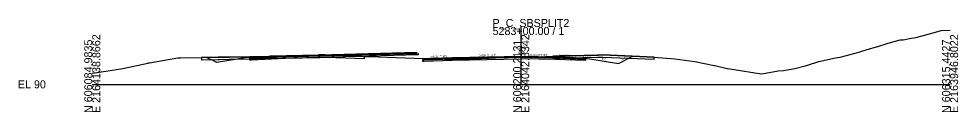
# Model space of a CAD drawing. Extents: x -26 to 1303, y -10 to 12033.
# Drawn here: x -25.7 to 302.8, y 1990.3 to 2022.8 of the extents above; entities that cross this region are included whole.
import ezdxf

# ---------------------------------------------------------------- set-up
doc = ezdxf.new("R2010")
doc.units = 0
for name, color, linetype in [('RD_GPK_XS_Cell', 7, 'Continuous'), ('RD_XS_Base', 7, 'Continuous'), ('RD_XS_ExGround', 7, 'Continuous'), ('RD_XS_ExPaveRet', 7, 'Continuous'), ('RD_XS_Greenside', 7, 'Continuous'), ('RD_XS_Pave', 7, 'Continuous'), ('RD_XS_PaveOvlay_CP', 7, 'Continuous'), ('RD_XS_TieSlope', 7, 'Continuous'), ('RD_XS_TX_Elev_EX', 7, 'Continuous'), ('RD_XS_TX_Elev_PR', 7, 'Continuous'), ('RD_XS_TX_ShdSlope', 7, 'Continuous'), ('RD_XS_TX_Slope', 7, 'Continuous')]:
    doc.layers.add(name, color=color, linetype=linetype)

msp = doc.modelspace()

# ---------------------------------------------------------------- linework, layer by layer
at = {"layer": 'RD_GPK_XS_Cell'}
for p, q in [((150, 2000), (150, 2020)), ((0, 2000), (150, 2000)), ((150, 2000), (300, 2000))]:
    msp.add_line(p, q, dxfattribs=at)
at = {"layer": 'RD_XS_Base'}
for p, q in [((79.53, 2009.89), (114.03, 2010.79)), ((113.53, 2010.78), (113.53, 2010.78)), ((114.03, 2010.79), (114.03, 2010.29)), ((114.03, 2010.76), (114.03, 2010.76)), ((55.52, 2009.1), (55.03, 2009.08)), ((55.03, 2009.08), (55.03, 2009.07)), ((55.03, 2009.07), (55.03, 2008.58)), ((55.03, 2008.58), (55.52, 2008.6)), ((55.53, 2009.1), (55.52, 2009.1)), ((55.52, 2008.6), (55.53, 2008.6)), ((67.43, 2009.58), (55.53, 2009.1)), ((55.53, 2008.6), (67.43, 2009.08)), ((67.53, 2009.58), (67.43, 2009.58)), ((67.43, 2009.08), (67.53, 2009.08)), ((79.53, 2009.89), (67.53, 2009.58)), ((67.53, 2009.08), (79.53, 2009.39)), ((114.03, 2010.29), (79.53, 2009.39)), ((79.53, 2009.39), (79.53, 2010.05)), ((79.53, 2010.05), (79.53, 2010.05)), ((79.53, 2010.05), (79.53, 2010.05)), ((79.53, 2010.05), (79.53, 2009.89)), ((79.53, 2009.89), (79.53, 2009.89)), ((79.53, 2009.39), (79.53, 2009.89)), ((79.53, 2009.89), (79.53, 2009.89)), ((79.53, 2009.89), (79.53, 2009.89)), ((79.53, 2009.39), (79.53, 2009.39)), ((103.53, 2010.52), (103.53, 2010.52)), ((103.53, 2010.52), (103.53, 2010.52)), ((103.53, 2010.02), (103.53, 2010.02)), ((103.53, 2010.02), (103.53, 2010.02)), ((116, 2008.55), (115.5, 2008.53)), ((115.5, 2008.53), (115.5, 2008.53)), ((115.5, 2008.53), (115.5, 2008.03)), ((115.5, 2008.03), (116, 2008.05)), ((126, 2008.95), (116, 2008.55)), ((116, 2008.55), (116, 2008.55)), ((116, 2008.05), (126, 2008.45)), ((116, 2008.05), (116, 2008.05)), ((150, 2009.43), (126, 2008.95)), ((126, 2008.95), (126, 2008.95)), ((126, 2008.45), (150, 2008.93)), ((126, 2008.45), (126, 2008.45)), ((150, 2008.93), (150, 2009.59)), ((150, 2009.59), (150, 2009.59)), ((150, 2009.59), (150, 2009.59)), ((150, 2009.59), (150, 2009.43)), ((150, 2009.43), (150, 2009.43)), ((150, 2009.43), (162, 2009.19)), ((150, 2009.43), (150, 2009.43)), ((150, 2008.93), (150, 2009.43)), ((150, 2009.43), (150, 2009.43)), ((150, 2009.43), (150, 2009.43)), ((162, 2008.69), (150, 2008.93)), ((150, 2008.93), (150, 2008.93)), ((150, 2008.93), (150, 2008.93)), ((162, 2009.19), (162, 2009.19)), ((162, 2009.19), (172, 2008.79)), ((172.5, 2008.27), (162, 2008.69)), ((162, 2008.69), (162, 2008.69)), ((172, 2008.79), (172, 2008.79)), ((172, 2008.79), (172.5, 2008.77)), ((172.5, 2008.77), (172.5, 2008.77)), ((172.5, 2008.77), (172.5, 2008.27))]:
    msp.add_line(p, q, dxfattribs=at)
at = {"layer": 'RD_XS_ExGround'}
msp.add_lwpolyline([(0, 2003.91), (5.51, 2004.71), (10.68, 2005.49), (19.48, 2007.43), (19.71, 2007.48), (20.06, 2007.55), (29.93, 2009.27), (30.97, 2009.28), (38.21, 2009.33), (44.09, 2009.45), (47.86, 2009.5), (47.89, 2009.5), (47.9, 2009.5), (61.79, 2009.77), (62.04, 2009.77), (62.41, 2009.78), (79.01, 2010.23), (79.28, 2010.26), (79.38, 2010.25), (79.88, 2010.27), (81.37, 2010.25), (85.15, 2010.12), (95.16, 2009.74), (100.25, 2009.59), (106.15, 2009.38), (112.75, 2009.12), (123.07, 2008.79), (126.49, 2008.63), (131.61, 2008.78), (143.32, 2009.31), (149.88, 2009.45), (152.23, 2009.52), (155.84, 2009.64), (161.06, 2009.83), (163.66, 2009.9), (166.43, 2009.96), (167.1, 2010), (176.71, 2010.23), (176.88, 2010.21), (178.4, 2010.24), (178.5, 2010.24), (178.6, 2010.24), (196.52, 2009.52), (203.73, 2008.86), (210.73, 2008), (217.55, 2006.61), (217.67, 2006.59), (218.16, 2006.47), (222.09, 2005.5), (222.14, 2005.5), (226.04, 2004.93), (231.73, 2003.98), (234.22, 2003.68), (239.82, 2004.66), (241.79, 2004.82), (245.68, 2005.49), (249.28, 2006.45), (249.39, 2006.46), (250.1, 2006.68), (254.09, 2007.99), (259.97, 2009.26), (261.51, 2009.5), (268.51, 2011.34), (268.73, 2011.4), (268.79, 2011.42), (272.16, 2012.55), (274.77, 2013.22), (278.29, 2014.34), (282.51, 2015.5), (283.61, 2015.5), (285.83, 2015.94), (288.03, 2016.38), (294.04, 2018), (296.83, 2018.78), (300, 2018.95)], dxfattribs=at)
at = {"layer": 'RD_XS_ExPaveRet'}
for points in [[(85.4, 2010.11), (85.15, 2010.12), (81.39, 2010.25), (81.37, 2010.25), (81.36, 2010.25), (79.88, 2010.27), (79.58, 2010.26), (79.38, 2010.25), (79.28, 2010.26), (79.01, 2010.23), (79.01, 2010.23), (79.01, 2010.23), (79, 2010.23), (62.41, 2009.78), (62.26, 2009.78), (62.04, 2009.77), (61.89, 2009.77), (61.79, 2009.77), (55.33, 2009.64), (55.05, 2009.64), (48.13, 2009.5), (48.02, 2009.5), (47.91, 2009.5), (44.5, 2009.45), (44.18, 2009.45), (44.09, 2009.45), (38.38, 2009.33), (38.21, 2009.33), (38.21, 2009.33), (38.21, 2009.33), (38.21, 2009.28), (38.21, 2008.58), (38.21, 2008.58), (38.21, 2008.58), (38.38, 2008.58), (44.09, 2008.7), (44.18, 2008.7), (44.5, 2008.7), (47.91, 2008.75), (48.02, 2008.75), (48.13, 2008.75), (55.05, 2008.89), (55.33, 2008.89), (61.79, 2009.02), (61.89, 2009.02), (62.04, 2009.02), (62.26, 2009.03), (62.41, 2009.03), (79, 2009.48), (79.01, 2009.48), (79.01, 2009.48), (79.01, 2009.48), (79.28, 2009.51), (79.38, 2009.5), (79.58, 2009.51), (79.88, 2009.52), (81.36, 2009.5), (81.37, 2009.5), (81.39, 2009.5), (85.15, 2009.37), (85.4, 2009.36), (95.16, 2008.99), (95.16, 2009.04), (95.16, 2009.74), (85.4, 2010.11)], [(85.4, 2010.11), (85.15, 2010.12), (81.39, 2010.25), (81.37, 2010.25), (81.36, 2010.25), (79.88, 2010.27), (79.58, 2010.26), (79.38, 2010.25), (79.28, 2010.26), (79.01, 2010.23), (79.01, 2010.23), (79.01, 2010.23), (79, 2010.23), (62.41, 2009.78), (62.26, 2009.78), (62.04, 2009.77), (61.89, 2009.77), (61.79, 2009.77), (55.33, 2009.64), (55.05, 2009.64), (48.13, 2009.5), (48.02, 2009.5), (47.91, 2009.5), (44.5, 2009.45), (44.18, 2009.45), (44.09, 2009.45), (38.38, 2009.33), (38.21, 2009.33), (38.21, 2009.28), (38.21, 2008.58), (38.38, 2008.58), (44.09, 2008.7), (44.18, 2008.7), (44.5, 2008.7), (47.91, 2008.75), (48.02, 2008.75), (48.13, 2008.75), (55.05, 2008.89), (55.33, 2008.89), (61.79, 2009.02), (61.89, 2009.02), (62.04, 2009.02), (62.26, 2009.03), (62.41, 2009.03), (79, 2009.48), (79.01, 2009.48), (79.01, 2009.48), (79.01, 2009.48), (79.28, 2009.51), (79.38, 2009.5), (79.58, 2009.51), (79.88, 2009.52), (81.36, 2009.5), (81.37, 2009.5), (81.39, 2009.5), (85.15, 2009.37), (85.4, 2009.36), (95.16, 2008.99), (95.16, 2009.04), (95.16, 2009.74), (85.4, 2010.11)], [(196.52, 2009.52), (196.52, 2009.52), (178.6, 2010.24), (178.6, 2010.24), (178.5, 2010.24), (178.4, 2010.24), (176.88, 2010.21), (176.88, 2010.21), (176.71, 2010.23), (176.71, 2010.23), (176.71, 2010.23), (176.71, 2010.23), (167.1, 2010), (167.1, 2010), (166.43, 2009.96), (163.66, 2009.9), (163.66, 2009.9), (161.06, 2009.83), (161.06, 2009.83), (161.06, 2009.08), (163.66, 2009.15), (163.66, 2009.15), (166.43, 2009.21), (167.1, 2009.25), (167.1, 2009.25), (176.71, 2009.48), (176.71, 2009.48), (176.71, 2009.48), (176.71, 2009.48), (176.88, 2009.46), (176.88, 2009.46), (178.4, 2009.49), (178.5, 2009.49), (178.6, 2009.49), (178.6, 2009.49), (196.52, 2008.77), (196.52, 2008.77), (196.52, 2008.77), (196.52, 2009.52), (196.52, 2009.52), (196.52, 2009.52)], [(196.52, 2009.52), (178.6, 2010.24), (178.5, 2010.24), (178.4, 2010.24), (176.88, 2010.21), (176.71, 2010.23), (167.1, 2010), (166.43, 2009.96), (163.66, 2009.9), (161.06, 2009.83), (161.06, 2009.08), (163.66, 2009.15), (166.43, 2009.21), (167.1, 2009.25), (176.71, 2009.48), (176.88, 2009.46), (178.4, 2009.49), (178.5, 2009.49), (178.6, 2009.49), (196.52, 2008.77), (196.52, 2008.77), (196.52, 2009.52), (196.52, 2009.52)]]:
    msp.add_lwpolyline(points, dxfattribs=at)
at = {"layer": 'RD_XS_Greenside'}
for p, q in [((43.53, 2007.59), (39.99, 2009.37)), ((53.53, 2009.26), (43.53, 2007.59)), ((174, 2008.95), (184, 2007.28)), ((184, 2007.28), (189.07, 2009.82))]:
    msp.add_line(p, q, dxfattribs=at)
at = {"layer": 'RD_XS_Pave'}
for p, q in [((113.53, 2011.1), (79.53, 2010.21)), ((113.53, 2010.94), (79.53, 2010.05)), ((79.53, 2010.05), (113.53, 2010.94)), ((79.53, 2009.89), (113.53, 2010.78)), ((103.53, 2010.84), (103.53, 2010.84)), ((103.53, 2010.84), (103.53, 2010.84)), ((103.53, 2010.68), (103.53, 2010.68)), ((103.53, 2010.68), (103.53, 2010.68)), ((103.53, 2010.68), (103.53, 2010.68)), ((103.53, 2010.68), (103.53, 2010.68)), ((113.53, 2010.94), (113.53, 2011.1)), ((113.53, 2011.1), (113.53, 2011.1)), ((113.53, 2010.78), (113.53, 2010.94)), ((113.53, 2010.94), (113.53, 2010.94)), ((55.53, 2009.42), (67.43, 2009.9)), ((67.43, 2009.74), (55.53, 2009.26)), ((67.43, 2009.74), (55.53, 2009.26)), ((55.53, 2009.1), (67.43, 2009.58)), ((55.53, 2009.26), (55.53, 2009.42)), ((55.53, 2009.42), (55.53, 2009.42)), ((55.53, 2009.26), (55.53, 2009.26)), ((55.53, 2009.26), (55.53, 2009.1)), ((67.43, 2009.9), (67.53, 2009.9)), ((67.53, 2009.74), (67.43, 2009.74)), ((67.53, 2009.74), (67.43, 2009.74)), ((67.43, 2009.58), (67.53, 2009.58)), ((67.53, 2009.9), (79.53, 2010.21)), ((79.53, 2010.05), (67.53, 2009.74)), ((79.53, 2010.05), (67.53, 2009.74)), ((67.53, 2009.58), (79.53, 2009.89)), ((79.53, 2010.21), (79.53, 2010.21)), ((79.53, 2010.05), (79.53, 2010.05)), ((79.53, 2010.05), (79.53, 2010.05)), ((79.53, 2010.05), (79.53, 2009.89)), ((79.53, 2010.05), (79.53, 2010.05)), ((79.53, 2009.89), (79.53, 2010.05)), ((79.53, 2010.05), (79.53, 2010.05)), ((79.53, 2010.05), (79.53, 2010.05)), ((79.53, 2009.89), (79.53, 2009.89)), ((79.53, 2009.89), (79.53, 2009.89)), ((103.53, 2010.52), (103.53, 2010.52)), ((103.53, 2010.52), (103.53, 2010.52)), ((126, 2009.27), (116, 2008.87)), ((126, 2009.11), (116, 2008.71)), ((116, 2008.71), (126, 2009.11)), ((116, 2008.55), (126, 2008.95)), ((116, 2008.87), (116, 2008.87)), ((116, 2008.87), (116, 2008.71)), ((116, 2008.71), (116, 2008.71)), ((116, 2008.71), (116, 2008.55)), ((150, 2009.75), (126, 2009.27)), ((150, 2009.59), (126, 2009.11)), ((126, 2009.11), (150, 2009.59)), ((126, 2008.95), (150, 2009.43)), ((126, 2009.27), (126, 2009.27)), ((126, 2009.11), (126, 2009.11)), ((126, 2009.11), (126, 2009.11)), ((126, 2008.95), (126, 2008.95)), ((162, 2009.51), (150, 2009.75)), ((150, 2009.75), (150, 2009.75)), ((150, 2009.75), (150, 2009.75)), ((150, 2009.43), (150, 2009.59)), ((150, 2009.59), (150, 2009.59)), ((150, 2009.59), (150, 2009.59)), ((162, 2009.35), (150, 2009.59)), ((150, 2009.59), (150, 2009.59)), ((150, 2009.59), (150, 2009.59)), ((150, 2009.59), (150, 2009.59)), ((150, 2009.59), (150, 2009.43)), ((150, 2009.59), (150, 2009.59)), ((150, 2009.59), (150, 2009.59)), ((150, 2009.59), (162, 2009.35)), ((150, 2009.43), (150, 2009.43)), ((150, 2009.43), (150, 2009.43)), ((150, 2009.43), (150, 2009.43)), ((150, 2009.43), (162, 2009.19)), ((172, 2009.11), (162, 2009.51)), ((162, 2009.51), (162, 2009.51)), ((172, 2008.95), (162, 2009.35)), ((162, 2009.35), (162, 2009.35)), ((162, 2009.35), (162, 2009.35)), ((162, 2009.35), (172, 2008.95)), ((162, 2009.19), (172, 2008.79)), ((162, 2009.19), (162, 2009.19)), ((172, 2008.95), (172, 2009.11)), ((172, 2009.11), (172, 2009.11)), ((172, 2008.79), (172, 2008.95)), ((172, 2008.95), (172, 2008.95))]:
    msp.add_line(p, q, dxfattribs=at)
at = {"layer": 'RD_XS_PaveOvlay_CP'}
for p, q in [((113.53, 2011.1), (79.53, 2010.21)), ((103.53, 2010.84), (103.53, 2010.84)), ((103.53, 2010.84), (103.53, 2010.84)), ((55.53, 2009.42), (67.43, 2009.9)), ((67.43, 2009.9), (67.53, 2009.9)), ((67.53, 2009.9), (79.53, 2010.21)), ((79.53, 2010.21), (79.53, 2010.21)), ((126, 2009.27), (116, 2008.87)), ((150, 2009.75), (126, 2009.27)), ((126, 2009.27), (126, 2009.27)), ((162, 2009.51), (150, 2009.75)), ((150, 2009.75), (150, 2009.75)), ((150, 2009.75), (150, 2009.75)), ((172, 2009.11), (162, 2009.51)), ((162, 2009.51), (162, 2009.51))]:
    msp.add_line(p, q, dxfattribs=at)
at = {"layer": 'RD_XS_TieSlope'}
for p, q in [((55.53, 2009.42), (53.53, 2009.26)), ((172, 2009.11), (174, 2008.95))]:
    msp.add_line(p, q, dxfattribs=at)

# ---------------------------------------------------------------- texts
at = {"layer": 'RD_GPK_XS_Cell'}
for s, p in [('P_C_SBSPLIT2', (140, 2020)), ('5283+00.00 / 1', (140, 2017.2)), ('EL 90', (-26, 1998.6))]:
    msp.add_text(s, height=2.8, dxfattribs=at).set_placement(p)
for s, p in [('E 2164138.8662', (2.8, 1990)), ('E 2164042.8342', (152.8, 1990)), ('E 2163946.8022', (302.8, 1990)), ('N 606084.9835', (0, 1990)), ('N 606200.2131', (150, 1990)), ('N 606315.4427', (300, 1990))]:
    msp.add_text(s, height=2.8, rotation=90, dxfattribs=at).set_placement(p)
at = {"layer": 'RD_XS_TX_Elev_EX'}
msp.add_text('99.46', height=0.6, rotation=90, dxfattribs=at).set_placement((149.63, 2010.53))
at = {"layer": 'RD_XS_TX_Elev_PR'}
msp.add_text('99.75', height=1, rotation=90, dxfattribs=at).set_placement((151.19, 2010.13))
at = {"layer": 'RD_XS_TX_ShdSlope'}
msp.add_text('12.5:1', height=0.75, rotation=355.4261, dxfattribs=at).set_placement((171.56, 2009.42))
at = {"layer": 'RD_XS_TX_Slope'}
for s, rotation, p in [('0.020 FT./FT.', 358.8542, (153.16, 2009.9)), ('0.040 FT./FT.', 2.2906, (118.15, 2009.17)), ('0.020 FT./FT.', 1.1458, (135.16, 2009.67)), ('0.040 FT./FT.', 357.7094, (163.17, 2009.68)), ('6:1', 350.5358, (178.13, 2008.65)), ('2:1', 26.5651, (185.45, 2008.44))]:
    msp.add_text(s, height=0.75, rotation=rotation, dxfattribs=at).set_placement(p)

doc.saveas('drawing.dxf')
